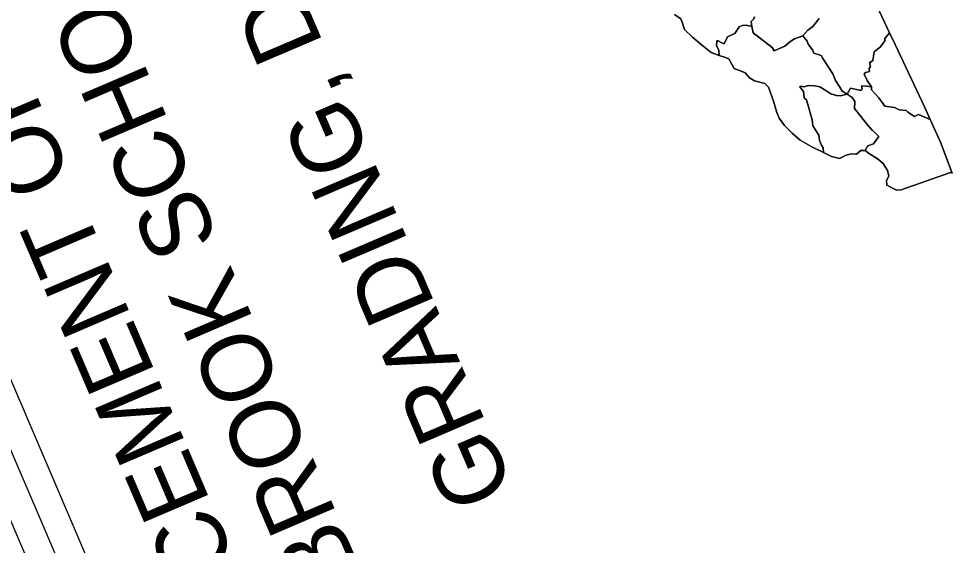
# Model space of a CAD drawing. Extents: x 1550250 to 1553210, y 808906 to 812497.
# Drawn here: x 1551099 to 1551388.6, y 810372.5 to 810536 of the extents above; entities that cross this region are included whole.
import ezdxf

# ---------------------------------------------------------------- set-up
doc = ezdxf.new("R2010")
doc.units = 0
for name, color, linetype in [('P_RDY_Dimension_Text', 7, 'Continuous'), ('Sheet_Data_Field_CELL', 7, 'Continuous'), ('Sheet_Title_CELL', 7, 'Continuous')]:
    doc.layers.add(name, color=color, linetype=linetype)

msp = doc.modelspace()

# ---------------------------------------------------------------- linework, layer by layer
at = {"layer": 'P_RDY_Dimension_Text'}
for points in [[(1551302.43, 810537.32), (1551304.38, 810535.9), (1551304.93, 810534.6), (1551305.52, 810532.61), (1551308.01, 810530.24), (1551310.74, 810527.94), (1551313.85, 810525.49), (1551316.25, 810524.56), (1551317.94, 810524.03), (1551319.3, 810523.48), (1551320.21, 810521.85), (1551320.95, 810520.52), (1551322.58, 810519.88), (1551324.32, 810519.19), (1551325.73, 810517.63), (1551327.28, 810516.71), (1551330.43, 810515.84), (1551331.61, 810514.73), (1551333.11, 810510.35), (1551334.16, 810506.88), (1551334.87, 810505.11), (1551336.59, 810502.78), (1551338.94, 810500.39), (1551341.37, 810498.28), (1551345.06, 810496.21), (1551348.66, 810494.45), (1551351.15, 810493.23), (1551353.64, 810492.61), (1551355.64, 810493.56), (1551357.27, 810494.06), (1551358.91, 810493.96), (1551360.27, 810495.06), (1551361.53, 810495.1), (1551362.97, 810493.99), (1551365.26, 810492.62), (1551367.18, 810491.06), (1551368.53, 810488.9), (1551368.93, 810487.04), (1551368.22, 810485.79), (1551368.35, 810484.28), (1551371.28, 810482.78), (1551372.77, 810482.89), (1551388.06, 810488.2), (1551388.62, 810488.03), (1551384.97, 810497.62), (1551381.78, 810504.69), (1551380.14, 810508.39), (1551370.87, 810528), (1551369.12, 810531.58), (1551359.77, 810551.8)], [(1551359.77, 810551.8), (1551369.12, 810531.58), (1551367.71, 810529.8), (1551367.67, 810529.1), (1551366.29, 810527.23), (1551364.38, 810525.72), (1551364.01, 810523.04), (1551362.97, 810522.3), (1551363.25, 810521.1), (1551362.82, 810520.54), (1551362.88, 810519.53), (1551361.69, 810519.26), (1551361.27, 810518.71), (1551362.2, 810516.76), (1551363.54, 810514.85), (1551361.95, 810515.05), (1551360.49, 810515.13), (1551360.6, 810514.22), (1551360.49, 810513.76), (1551359.79, 810513.81), (1551356.98, 810514.42), (1551356.02, 810512.58), (1551354.47, 810513.49), (1551353.75, 810514.74), (1551352.36, 810516.81), (1551351.56, 810518.89), (1551348.44, 810523.62), (1551347.9, 810524.57), (1551345.65, 810525.28), (1551345.19, 810526.26), (1551343.9, 810528.02), (1551343.59, 810529.04)], [(1551327.27, 810536.59), (1551327.05, 810535.92), (1551326.2, 810535.07), (1551326.39, 810533.58), (1551324.65, 810534.01), (1551323.43, 810533.82), (1551322.52, 810533.47), (1551321.11, 810531.33), (1551318.87, 810530.33), (1551317.8, 810528.21), (1551317.14, 810528.44), (1551315.99, 810529.14), (1551315.58, 810529.1), (1551315.43, 810527.59), (1551316.19, 810526.18), (1551316.25, 810524.56), (1551313.85, 810525.49), (1551310.74, 810527.94), (1551308.01, 810530.24), (1551305.52, 810532.61), (1551304.93, 810534.6), (1551304.38, 810535.9), (1551302.43, 810537.32)], [(1551326.82, 810531.55), (1551326.39, 810533.58), (1551326.2, 810535.07), (1551327.05, 810535.92), (1551327.27, 810536.59)], [(1551347.35, 810535.99), (1551345.38, 810533.52), (1551343.78, 810532.36), (1551342.27, 810530.62), (1551339.65, 810529.76), (1551338.52, 810529), (1551336.7, 810527.43), (1551333.32, 810525.99), (1551332.75, 810527.03), (1551326.82, 810531.55)], [(1551343.59, 810529.04), (1551342.27, 810530.62), (1551343.78, 810532.36), (1551345.38, 810533.52), (1551347.35, 810535.99)], [(1551341.36, 810514.8), (1551342.48, 810513.33), (1551342.64, 810511.4), (1551343.42, 810510.78), (1551343.99, 810508.63), (1551345.14, 810504.58), (1551345.35, 810502.75), (1551347.2, 810499.78), (1551347.44, 810498.13), (1551348.03, 810496.76), (1551348.56, 810495.89), (1551348.66, 810494.45), (1551345.06, 810496.21), (1551341.37, 810498.28), (1551338.94, 810500.39), (1551336.59, 810502.78), (1551334.87, 810505.11), (1551334.16, 810506.88), (1551333.11, 810510.35), (1551331.61, 810514.73), (1551330.43, 810515.84), (1551327.28, 810516.71), (1551325.73, 810517.63), (1551324.32, 810519.19), (1551322.58, 810519.88), (1551320.95, 810520.52), (1551320.21, 810521.85), (1551319.3, 810523.48), (1551317.94, 810524.03), (1551316.25, 810524.56), (1551316.19, 810526.18), (1551315.43, 810527.59), (1551315.58, 810529.1), (1551315.99, 810529.14), (1551317.14, 810528.44), (1551317.8, 810528.21), (1551318.87, 810530.33), (1551321.11, 810531.33), (1551322.52, 810533.47), (1551323.43, 810533.82), (1551324.65, 810534.01), (1551326.39, 810533.58), (1551326.82, 810531.55), (1551332.75, 810527.03), (1551333.32, 810525.99), (1551336.7, 810527.43), (1551338.52, 810529), (1551339.65, 810529.76), (1551342.27, 810530.62), (1551343.59, 810529.04), (1551343.9, 810528.02), (1551345.19, 810526.26), (1551345.65, 810525.28), (1551347.9, 810524.57), (1551348.44, 810523.62), (1551351.56, 810518.89), (1551352.36, 810516.81), (1551353.75, 810514.74), (1551354.47, 810513.49), (1551356.02, 810512.58), (1551353.82, 810512.01), (1551352.67, 810512.18), (1551350.93, 810512.6), (1551349.33, 810513.67), (1551347.53, 810514.85), (1551346, 810515.16), (1551343.94, 810515.23), (1551342.7, 810514.86), (1551341.46, 810515.01), (1551341.36, 810514.8)], [(1551361.27, 810518.71), (1551361.69, 810519.26), (1551362.88, 810519.53), (1551362.82, 810520.54), (1551363.25, 810521.1), (1551362.97, 810522.3), (1551364.01, 810523.04), (1551364.38, 810525.72), (1551366.29, 810527.23), (1551367.67, 810529.1), (1551367.71, 810529.8), (1551369.12, 810531.58), (1551370.87, 810528), (1551380.14, 810508.39), (1551381.78, 810504.69), (1551378.17, 810506.25), (1551377.29, 810505.81), (1551376.93, 810505.61), (1551374.83, 810506.95), (1551374.33, 810507.48), (1551372.16, 810507.68), (1551370.66, 810508.42), (1551367.67, 810508.8), (1551365.85, 810511.43), (1551363.57, 810513.91), (1551363.54, 810514.85), (1551362.2, 810516.76), (1551361.27, 810518.71)], [(1551356.02, 810512.58), (1551357.53, 810511.49), (1551358.4, 810510.3), (1551358.23, 810508.1), (1551362.33, 810502.99), (1551363.76, 810501.36), (1551364.7, 810500.53), (1551365.8, 810499.4), (1551364.12, 810497.17), (1551362.36, 810496.55), (1551361.53, 810495.1), (1551360.27, 810495.06), (1551358.91, 810493.96), (1551357.27, 810494.06), (1551355.64, 810493.56), (1551353.64, 810492.61), (1551351.15, 810493.23), (1551348.66, 810494.45), (1551348.56, 810495.89), (1551348.03, 810496.76), (1551347.44, 810498.13), (1551347.2, 810499.78), (1551345.35, 810502.75), (1551345.14, 810504.58), (1551343.99, 810508.63), (1551343.42, 810510.78), (1551342.64, 810511.4), (1551342.48, 810513.33), (1551341.36, 810514.8), (1551341.46, 810515.01), (1551342.7, 810514.86), (1551343.94, 810515.23), (1551346, 810515.16), (1551347.53, 810514.85), (1551349.33, 810513.67), (1551350.93, 810512.6), (1551352.67, 810512.18), (1551353.82, 810512.01), (1551356.02, 810512.58)], [(1551356.02, 810512.58), (1551356.98, 810514.42), (1551359.79, 810513.81), (1551360.49, 810513.76), (1551360.6, 810514.22), (1551360.49, 810515.13), (1551361.95, 810515.05), (1551363.54, 810514.85), (1551363.57, 810513.91), (1551365.85, 810511.43), (1551367.67, 810508.8), (1551370.66, 810508.42), (1551372.16, 810507.68), (1551374.33, 810507.48), (1551374.83, 810506.95), (1551376.93, 810505.61), (1551377.29, 810505.81), (1551378.17, 810506.25), (1551381.78, 810504.69), (1551384.97, 810497.62), (1551388.62, 810488.03), (1551388.06, 810488.2), (1551372.77, 810482.89), (1551371.28, 810482.78), (1551368.35, 810484.28), (1551368.22, 810485.79), (1551368.93, 810487.04), (1551368.53, 810488.9), (1551367.18, 810491.06), (1551365.26, 810492.62), (1551362.97, 810493.99), (1551361.53, 810495.1), (1551362.36, 810496.55), (1551364.12, 810497.17), (1551365.8, 810499.4), (1551364.7, 810500.53), (1551363.76, 810501.36), (1551362.33, 810502.99), (1551358.23, 810508.1), (1551358.4, 810510.3), (1551357.53, 810511.49), (1551356.02, 810512.58)]]:
    msp.add_lwpolyline(points, dxfattribs=at)
at = {"layer": 'Sheet_Title_CELL'}
for p, q in [((1551225.17, 810079.5), (1550942.8, 810739.21)), ((1551229.73, 810090.84), (1550954.11, 810734.67)), ((1551234.24, 810102.15), (1550965.45, 810730.14))]:
    msp.add_line(p, q, dxfattribs=at)

# ---------------------------------------------------------------- texts
at = {"layer": 'Sheet_Data_Field_CELL'}
for s, height, p in [('GRADING, DRAINAGE, PAVING, AND STRUCTURE', 21.5627, (1551252.97, 810389.57)), ('REPLACEMENT OF BRIDGE NO. 76 ON SR 1436', 21.5627, (1551204.03, 810279.9)), ('(PINEBROOK SCHOOL RD)', 21.5627, (1551235.72, 810293.46)), ('DAVIE COUNTY', 43.125, (1551156.25, 810153.28))]:
    msp.add_text(s, height=height, rotation=113.1736, dxfattribs=at).set_placement(p)

doc.saveas('drawing.dxf')
